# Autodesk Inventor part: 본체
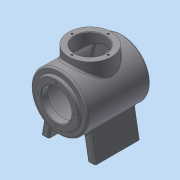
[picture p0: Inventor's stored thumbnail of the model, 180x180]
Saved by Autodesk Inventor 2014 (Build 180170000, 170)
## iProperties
Created: 2015-01
Part Number: 본체
Material: 일반
Document SubType Name: Modeling
Designer: user
Density: 1 g/cm^3
Appearance: 기본값
Author: user
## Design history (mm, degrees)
sketch "스케치1"
  geometry: L1 (0, 0)-(122, 0); L2 (0, 27)-(12, 27); L3 (12, 45)-(109, 45); L4 (12, 27)-(12, 45); L5 (109, 27)-(122, 27); L6 (109, 45)-(109, 27); L7 (0, 38)-(5, 38); L8 (0, 27)-(0, 38); L9 (5, 50)-(117, 50); L10 (5, 38)-(5, 50); L11 (117, 38)-(122, 38); L12 (117, 50)-(117, 38); L13 (122, 38)-(122, 27)
  constraints: 26 end point, 8 perpendicular, 3 vertical alignment, 2 parallel, 1 horizontal
  dimensions: "d0" = 122 distance of L1.start L1.end; "d3" = 12 distance of L2.start L2.end; "d4" = 27 distance between parallel lines of L1 L2; "d5" = 97 distance of L3.start L3.end; "d6" = 45 distance between parallel lines of L1 L3; "d7" = 13 distance of L5.start L5.end; "d8" = 27 distance between parallel lines of L1 L5; "d9" = 5 distance of L7.start L7.end; "d10" = 38 distance between parallel lines of L1 L7; "d11" = 112 distance of L9.start L9.end; "d12" = 50 distance between parallel lines of L1 L9; "d13" = 5 distance of L11.start L11.end; "d14" = 38 distance between parallel lines of L1 L11
revolve "회전1" sketch "스케치1" stored, may be unused: angle "d15" = 90 deg
node "작업 평면1"
sketch "스케치2"
  geometry: L1 (-80, -48)-(-80, -34); L2 (-80, -34)-(-41.901, -27.282); L3 (-41.901, 27.282)-(-80, 34); L4 (-80, 34)-(-80, 48); L5 (-80, 48)-(-30.865, 39.336); L6 (-30.865, -39.336)-(-80, -48); C1 r 45 at (0, 0) reference; C2 r 38 at (0, 0) reference; A1 r 50 centre (0, 0) between (-30.865, -39.336) and (-30.865, 39.336) reference; A2 r 50 centre (0, 0) between (-41.901, -27.282) and (-30.865, -39.336); A3 r 50 centre (0, 0) between (-30.865, 39.336) and (-41.901, 27.282); 1 further point
  constraints: 12 end point, 8 point on circle, 2 centre point, 2 collinear, 2 concentric, 2 parallel, 1 vertical
  dimensions: "d17" = 14 distance of L1.start L1.end; "d18" = 14 distance of L3.end L4.end; "d19" = 100 deg angle of L4 L3; "d20" = 100 deg angle of L2 L1; "d21" = 96 distance of L4.end L1.start; "d22" = 80 distance from line of L1 point (0, 0); "d23" = 48 vertical distance of L1.start point (0, 0)
extrude "돌출1" join sketch "스케치2" distance "d24" = 80; taper "d25" = 0 deg
node "작업 평면3"
sketch "스케치3"
  geometry: L1 (101, -30.865)-(21, -30.865) reference; L2 (21, -30.865)-(21, -41.901) reference; L3 (21, -41.901)-(101, -41.901) reference; L4 (101, -41.901)-(101, -30.865) reference; L5 (21, -30.865)-(101, -30.865) reference; L6 (101, -30.865)-(101, -41.901) reference; L7 (101, -41.901)-(21, -41.901) reference; L8 (21, -41.901)-(21, -30.865) reference; L9 (5, 50)-(5, -50) reference; L10 (117, 50)-(117, -50) reference; L11 (88, 6)-(34, 6); L12 (34, 6)-(34, -6); L13 (34, -6)-(88, -6); L14 (88, -6)-(88, 6); L15 (21, -80)-(101, -80) reference; 3 further points
  constraints: 8 end point, 2 midpoint, 2 parallel, 1 horizontal, 1 perpendicular, 1 vertical alignment
  dimensions: "d28" = 54 distance of L11.start L11.end; "d29" = 12 distance of L13.end L11.start; "d30" = 74 distance from line of L13.end L15
extrude "돌출2" join sketch "스케치3" distance "d31" = 2; taper "d33" = 0 deg; dims "d32" = 2, "d34" = 0
sketch "스케치4"
  geometry: L1 (-34, 6)-(-88, 6) reference; L2 (-88, 6)-(-88, -6) reference; L3 (-88, -6)-(-34, -6) reference; L4 (-34, -6)-(-34, 6) reference; 4 further points
  constraints: 2 midpoint, 1 horizontal alignment, 1 vertical alignment, 1 other
feature "엠보싱1" sketch "스케치4" dims "d0" = 122, "d3" = 12, "d4" = 27, "d5" = 97, "d6" = 45, "d7" = 13, "d8" = 27, "d9" = 5, "d10" = 38, "d11" = 112, "d12" = 50, "d13" = 5, "d14" = 38, "d17" = 14, "d18" = 14, "d19" = 100 deg, "d20" = 100 deg, "d21" = 96, "d22" = 80, "d23" = 48, "d35" = 0.5, "d36" = 0
node "작업 평면4"
sketch "스케치5"
  geometry: L1 (-122, -38)-(-122, 38) reference; L2 (0, -38)-(0, 38) reference; C1 r 38 at (-60, 0); 1 further point
  constraints: 1 centre point, 1 horizontal alignment
  dimensions: "d38" = 38 radius of C1; "d39" = 60 distance of point (0, 0) C1.centre
extrude "돌출3" join sketch "스케치5" stored distance "d40" = 2; taper "d41" = 0 deg
sketch "스케치6"
  geometry: C1 r 38 at (0, 0) reference; C2 r 27 at (0, 0); 1 further point
  constraints: 1 centre point, 1 coincident
  dimensions: "d42" = 27 radius of C2
extrude "돌출4" cut sketch "스케치6" stored distance "d43" = 2; taper "d44" = 0 deg
sketch "스케치7"
  geometry: 2 further points
  constraints: 1 vertical alignment
  dimensions: "d45" = 32 distance of point (0, 0) point (0, 32)
hole "구멍1" sketch "스케치7" at (0, 32) diameter "d46" = 3.242; stored, may be unused: countersink angle "d50" = 90 deg, drill point angle "d52" = 118 deg; dims "d47" = 8, "d48" = 4, "d49" = 2, "d51" = 10
node "작업 평면5"
sketch "스케치8"
  geometry: L1 (-39, -34)-(41, -34) reference; C1 r 27 at (0, 0) reference; C2 r 38 at (0, 0) reference; 2 further points
  constraints: 1 vertical alignment
  dimensions: "d57" = 32 distance of C1.centre point (0, -32)
hole "구멍2" sketch "스케치8" at (0, -32) diameter "d58" = 3.242; stored, may be unused: countersink angle "d62" = 90 deg, drill point angle "d64" = 118 deg; dims "d59" = 8, "d60" = 4, "d61" = 2, "d63" = 10
fillet "모깎기1" dims "d68" = 3
fillet "모깎기2" dims "d69" = 3
fillet "모깎기3" dims "d70" = 3
fillet "모깎기4" dims "d71" = 3
fillet "모깎기5" dims "d72" = 3
chamfer "모따기1" distance "d73" = 1; stored, may be unused: second distance "d74" = 2, angle "d75" = 45 deg
chamfer "모따기2" distance "d76" = 1; stored, may be unused: second distance "d77" = 2, angle "d78" = 45 deg
chamfer "모따기3" distance "d79" = 1; stored, may be unused: second distance "d80" = 2, angle "d81" = 45 deg
node "솔리드1"
pattern_circular "원형 패턴1" dims angle "d54" = 360 deg
mirror "대칭1"
pattern_circular "원형 패턴2" dims angle "d66" = 360 deg
node "투영된 루프1"
node "투영된 루프2"
node "투영된 루프3"
node "투영된 루프4"
other parameters: "d16" = 21, "d37" = 62, "d56" = 61
